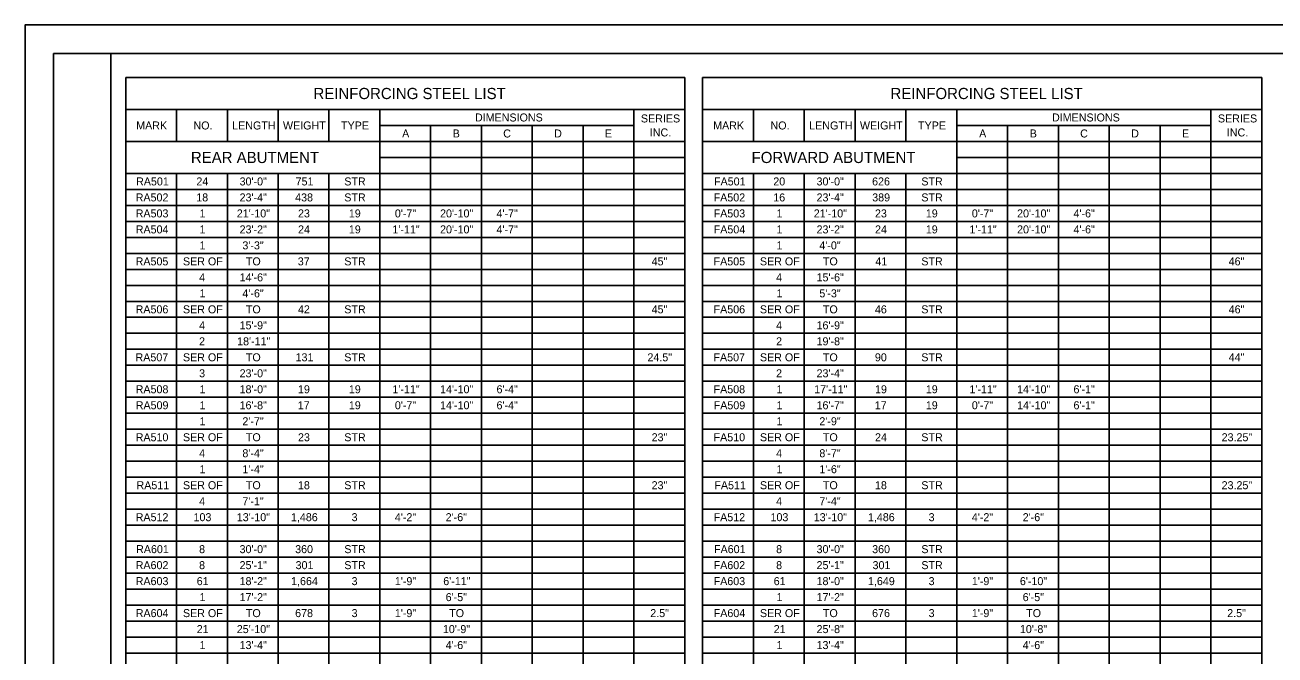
# Model space of a CAD drawing. Extents: x 0 to 34, y 0 to 22.
# Drawn here: x 0 to 21.87, y 10.97 to 22 of the extents above; entities that cross this region are included whole.
import ezdxf

# ---------------------------------------------------------------- set-up
doc = ezdxf.new("R2010")
doc.units = 0
for name, color, linetype in [('Default', 7, 'Continuous'), ('SH_Border', 7, 'Continuous'), ('SH_Cut_Line', 7, 'Continuous')]:
    doc.layers.add(name, color=color, linetype=linetype)

msp = doc.modelspace()

# ---------------------------------------------------------------- linework, layer by layer
at = {"layer": 'Default'}
for p, q in [((1.762, 21.08), (11.545, 21.08)), ((1.762, 21.08), (1.762, 0.92)), ((11.545, 21.08), (11.545, 0.92)), ((11.858, 21.08), (21.642, 21.08)), ((11.858, 21.08), (11.858, 0.92)), ((21.642, 21.08), (21.642, 0.92)), ((1.762, 20.52), (11.545, 20.52)), ((2.651, 20.52), (2.651, 19.96)), ((3.541, 20.52), (3.541, 19.96)), ((4.43, 20.52), (4.43, 19.96)), ((5.319, 20.52), (5.319, 19.96)), ((6.209, 20.52), (6.209, 2.04)), ((10.656, 20.52), (10.656, 2.04)), ((11.858, 20.52), (21.642, 20.52)), ((12.748, 20.52), (12.748, 19.96)), ((13.637, 20.52), (13.637, 19.96)), ((14.526, 20.52), (14.526, 19.96)), ((15.416, 20.52), (15.416, 19.96)), ((16.305, 20.52), (16.305, 2.04)), ((20.752, 20.52), (20.752, 2.04)), ((6.209, 20.24), (10.656, 20.24)), ((7.098, 20.24), (7.098, 2.04)), ((7.988, 20.24), (7.988, 2.04)), ((8.877, 20.24), (8.877, 2.04)), ((9.766, 20.24), (9.766, 2.04)), ((16.305, 20.24), (20.752, 20.24)), ((17.195, 20.24), (17.195, 2.04)), ((18.084, 20.24), (18.084, 2.04)), ((18.974, 20.24), (18.974, 2.04)), ((19.863, 20.24), (19.863, 2.04)), ((1.762, 19.96), (11.545, 19.96)), ((11.858, 19.96), (21.642, 19.96)), ((6.209, 19.68), (11.545, 19.68)), ((16.305, 19.68), (21.642, 19.68)), ((1.762, 19.4), (6.209, 19.4)), ((2.651, 19.4), (2.651, 7.08)), ((3.541, 19.4), (3.541, 7.08)), ((4.43, 19.4), (4.43, 7.08)), ((5.319, 19.4), (5.319, 7.08)), ((6.209, 19.4), (11.545, 19.4)), ((11.858, 19.4), (16.305, 19.4)), ((12.748, 19.4), (12.748, 7.08)), ((13.637, 19.4), (13.637, 7.08)), ((14.526, 19.4), (14.526, 7.08)), ((15.416, 19.4), (15.416, 7.08)), ((16.305, 19.4), (21.642, 19.4)), ((1.762, 19.12), (11.545, 19.12)), ((11.858, 19.12), (21.642, 19.12)), ((1.762, 18.84), (11.545, 18.84)), ((11.858, 18.84), (21.642, 18.84)), ((1.762, 18.56), (11.545, 18.56)), ((11.858, 18.56), (21.642, 18.56)), ((1.762, 18.28), (11.545, 18.28)), ((11.858, 18.28), (21.642, 18.28)), ((1.762, 18), (11.545, 18)), ((11.858, 18), (21.642, 18)), ((1.762, 17.72), (11.545, 17.72)), ((11.858, 17.72), (21.642, 17.72)), ((1.762, 17.44), (11.545, 17.44)), ((11.858, 17.44), (21.642, 17.44)), ((1.762, 17.16), (11.545, 17.16)), ((11.858, 17.16), (21.642, 17.16)), ((1.762, 16.88), (11.545, 16.88)), ((11.858, 16.88), (21.642, 16.88)), ((1.762, 16.6), (11.545, 16.6)), ((11.858, 16.6), (21.642, 16.6)), ((1.762, 16.32), (11.545, 16.32)), ((11.858, 16.32), (21.642, 16.32)), ((1.762, 16.04), (11.545, 16.04)), ((11.858, 16.04), (21.642, 16.04)), ((1.762, 15.76), (11.545, 15.76)), ((11.858, 15.76), (21.642, 15.76)), ((1.762, 15.48), (11.545, 15.48)), ((11.858, 15.48), (21.642, 15.48)), ((1.762, 15.2), (11.545, 15.2)), ((11.858, 15.2), (21.642, 15.2)), ((1.762, 14.92), (11.545, 14.92)), ((11.858, 14.92), (21.642, 14.92)), ((1.762, 14.64), (11.545, 14.64)), ((11.858, 14.64), (21.642, 14.64)), ((1.762, 14.36), (11.545, 14.36)), ((11.858, 14.36), (21.642, 14.36)), ((1.762, 14.08), (11.545, 14.08)), ((11.858, 14.08), (21.642, 14.08)), ((1.762, 13.8), (11.545, 13.8)), ((11.858, 13.8), (21.642, 13.8)), ((1.762, 13.52), (11.545, 13.52)), ((11.858, 13.52), (21.642, 13.52)), ((1.762, 13.24), (11.545, 13.24)), ((11.858, 13.24), (21.642, 13.24)), ((1.762, 12.96), (11.545, 12.96)), ((11.858, 12.96), (21.642, 12.96)), ((1.762, 12.68), (11.545, 12.68)), ((11.858, 12.68), (21.642, 12.68)), ((1.762, 12.4), (11.545, 12.4)), ((11.858, 12.4), (21.642, 12.4)), ((1.762, 12.12), (11.545, 12.12)), ((11.858, 12.12), (21.642, 12.12)), ((1.762, 11.84), (11.545, 11.84)), ((11.858, 11.84), (21.642, 11.84)), ((1.762, 11.56), (11.545, 11.56)), ((11.858, 11.56), (21.642, 11.56)), ((1.762, 11.28), (11.545, 11.28)), ((11.858, 11.28), (21.642, 11.28)), ((1.762, 11), (11.545, 11)), ((11.858, 11), (21.642, 11))]:
    msp.add_line(p, q, dxfattribs=at)
at = {"layer": 'SH_Border'}
for points in [[(0.5, 21.5), (1.5, 21.5), (1.5, 0.5), (0.5, 0.5)], [(1.5, 21.5), (33.5, 21.5), (33.5, 0.5), (1.5, 0.5)]]:
    msp.add_lwpolyline(points, close=True, dxfattribs=at)
at = {"layer": 'SH_Cut_Line'}
msp.add_lwpolyline([(0, 0), (34, 0), (34, 22), (0, 22)], close=True, dxfattribs=at)

# ---------------------------------------------------------------- texts
at = {"layer": 'Default'}
for s, height, p in [('REINFORCING STEEL LIST', 0.196, (5.048, 20.702)), ('REINFORCING STEEL LIST', 0.196, (15.145, 20.702)), ('DIMENSIONS', 0.14, (7.874, 20.31)), ('SERIES ', 0.14, (10.777, 20.293)), ('DIMENSIONS', 0.14, (17.971, 20.31)), ('SERIES ', 0.14, (20.874, 20.293)), ('MARK', 0.14, (1.946, 20.17)), ('NO.', 0.14, (2.948, 20.17)), ('LENGTH', 0.14, (3.625, 20.17)), ('WEIGHT', 0.14, (4.514, 20.17)), ('TYPE', 0.14, (5.53, 20.17)), ('A', 0.14, (6.599, 20.03)), ('B', 0.14, (7.484, 20.03)), ('C', 0.14, (8.368, 20.03)), ('D', 0.14, (9.259, 20.03)), ('E', 0.14, (10.148, 20.03)), ('INC.', 0.14, (10.933, 20.048)), ('MARK', 0.14, (12.042, 20.17)), ('NO.', 0.14, (13.045, 20.17)), ('LENGTH', 0.14, (13.722, 20.17)), ('WEIGHT', 0.14, (14.61, 20.17)), ('TYPE', 0.14, (15.627, 20.17)), ('A', 0.14, (16.696, 20.03)), ('B', 0.14, (17.581, 20.03)), ('C', 0.14, (18.464, 20.03)), ('D', 0.14, (19.356, 20.03)), ('E', 0.14, (20.245, 20.03)), ('INC.', 0.14, (21.03, 20.048)), ('REAR ABUTMENT', 0.196, (2.903, 19.582)), ('FORWARD ABUTMENT', 0.196, (12.714, 19.582)), ('RA501', 0.14, (1.944, 19.19)), ('24', 0.14, (2.999, 19.19)), ('30\'-0"', 0.14, (3.755, 19.19)), ('751', 0.14, (4.735, 19.19)), ('STR', 0.14, (5.587, 19.19)), ('FA501', 0.14, (12.057, 19.19)), ('20', 0.14, (13.094, 19.19)), ('30\'-0"', 0.14, (13.851, 19.19)), ('626', 0.14, (14.823, 19.19)), ('STR', 0.14, (15.684, 19.19)), ('RA502', 0.14, (1.937, 18.91)), ('18', 0.14, (2.997, 18.91)), ('23\'-4"', 0.14, (3.755, 18.91)), ('438', 0.14, (4.727, 18.91)), ('STR', 0.14, (5.587, 18.91)), ('FA502', 0.14, (12.05, 18.91)), ('16', 0.14, (13.093, 18.91)), ('23\'-4"', 0.14, (13.851, 18.91)), ('389', 0.14, (14.825, 18.91)), ('STR', 0.14, (15.684, 18.91)), ('RA503', 0.14, (1.937, 18.63)), ('1', 0.14, (3.054, 18.63)), ('21\'-10"', 0.14, (3.706, 18.63)), ('23', 0.14, (4.777, 18.63)), ('19', 0.14, (5.667, 18.63)), ('0\'-7"', 0.14, (6.472, 18.63)), ('20\'-10"', 0.14, (7.263, 18.63)), ('4\'-7"', 0.14, (8.251, 18.63)), ('FA503', 0.14, (12.05, 18.63)), ('1', 0.14, (13.15, 18.63)), ('21\'-10"', 0.14, (13.802, 18.63)), ('23', 0.14, (14.873, 18.63)), ('19', 0.14, (15.763, 18.63)), ('0\'-7"', 0.14, (16.568, 18.63)), ('20\'-10"', 0.14, (17.36, 18.63)), ('4\'-6"', 0.14, (18.347, 18.63)), ('RA504', 0.14, (1.938, 18.35)), ('1', 0.14, (3.054, 18.35)), ('23\'-2"', 0.14, (3.755, 18.35)), ('24', 0.14, (4.778, 18.35)), ('19', 0.14, (5.667, 18.35)), ('1\'-11"', 0.14, (6.429, 18.35)), ('20\'-10"', 0.14, (7.263, 18.35)), ('4\'-7"', 0.14, (8.251, 18.35)), ('FA504', 0.14, (12.051, 18.35)), ('1', 0.14, (13.15, 18.35)), ('23\'-2"', 0.14, (13.851, 18.35)), ('24', 0.14, (14.874, 18.35)), ('19', 0.14, (15.763, 18.35)), ('1\'-11"', 0.14, (16.526, 18.35)), ('20\'-10"', 0.14, (17.36, 18.35)), ('4\'-6"', 0.14, (18.347, 18.35)), ('1', 0.14, (3.054, 18.07)), ('3\'-3"', 0.14, (3.804, 18.07)), ('1', 0.14, (13.15, 18.07)), ('4\'-0"', 0.14, (13.9, 18.07)), ('RA505', 0.14, (1.936, 17.79)), ('SER OF', 0.14, (2.764, 17.79)), ('TO', 0.14, (3.865, 17.79)), ('37', 0.14, (4.773, 17.79)), ('STR', 0.14, (5.587, 17.79)), ('45"', 0.14, (10.965, 17.79)), ('FA505', 0.14, (12.049, 17.79)), ('SER OF', 0.14, (12.86, 17.79)), ('TO', 0.14, (13.962, 17.79)), ('41', 0.14, (14.88, 17.79)), ('STR', 0.14, (15.684, 17.79)), ('46"', 0.14, (21.062, 17.79)), ('4', 0.14, (3.048, 17.51)), ('14\'-6"', 0.14, (3.755, 17.51)), ('4', 0.14, (13.144, 17.51)), ('15\'-6"', 0.14, (13.851, 17.51)), ('1', 0.14, (3.054, 17.23)), ('4\'-6"', 0.14, (3.804, 17.23)), ('1', 0.14, (13.15, 17.23)), ('5\'-3"', 0.14, (13.9, 17.23)), ('RA506', 0.14, (1.936, 16.95)), ('SER OF', 0.14, (2.764, 16.95)), ('TO', 0.14, (3.865, 16.95)), ('42', 0.14, (4.776, 16.95)), ('STR', 0.14, (5.587, 16.95)), ('45"', 0.14, (10.965, 16.95)), ('FA506', 0.14, (12.049, 16.95)), ('SER OF', 0.14, (12.86, 16.95)), ('TO', 0.14, (13.962, 16.95)), ('46', 0.14, (14.872, 16.95)), ('STR', 0.14, (15.684, 16.95)), ('46"', 0.14, (21.062, 16.95)), ('4', 0.14, (3.048, 16.67)), ('15\'-9"', 0.14, (3.755, 16.67)), ('4', 0.14, (13.144, 16.67)), ('16\'-9"', 0.14, (13.851, 16.67)), ('2', 0.14, (3.046, 16.39)), ('18\'-11"', 0.14, (3.712, 16.39)), ('2', 0.14, (13.143, 16.39)), ('19\'-8"', 0.14, (13.851, 16.39)), ('RA507', 0.14, (1.934, 16.11)), ('SER OF', 0.14, (2.764, 16.11)), ('TO', 0.14, (3.865, 16.11)), ('131', 0.14, (4.735, 16.11)), ('STR', 0.14, (5.587, 16.11)), ('24.5"', 0.14, (10.892, 16.11)), ('FA507', 0.14, (12.047, 16.11)), ('SER OF', 0.14, (12.86, 16.11)), ('TO', 0.14, (13.962, 16.11)), ('90', 0.14, (14.872, 16.11)), ('STR', 0.14, (15.684, 16.11)), ('44"', 0.14, (21.062, 16.11)), ('3', 0.14, (3.047, 15.83)), ('23\'-0"', 0.14, (3.755, 15.83)), ('2', 0.14, (13.143, 15.83)), ('23\'-4"', 0.14, (13.851, 15.83)), ('RA508', 0.14, (1.937, 15.55)), ('1', 0.14, (3.054, 15.55)), ('18\'-0"', 0.14, (3.755, 15.55)), ('19', 0.14, (4.777, 15.55)), ('19', 0.14, (5.667, 15.55)), ('1\'-11"', 0.14, (6.429, 15.55)), ('14\'-10"', 0.14, (7.263, 15.55)), ('6\'-4"', 0.14, (8.251, 15.55)), ('FA508', 0.14, (12.049, 15.55)), ('1', 0.14, (13.15, 15.55)), ('17\'-11"', 0.14, (13.809, 15.55)), ('19', 0.14, (14.874, 15.55)), ('19', 0.14, (15.763, 15.55)), ('1\'-11"', 0.14, (16.526, 15.55)), ('14\'-10"', 0.14, (17.36, 15.55)), ('6\'-1"', 0.14, (18.347, 15.55)), ('RA509', 0.14, (1.938, 15.27)), ('1', 0.14, (3.054, 15.27)), ('16\'-8"', 0.14, (3.755, 15.27)), ('17', 0.14, (4.773, 15.27)), ('19', 0.14, (5.667, 15.27)), ('0\'-7"', 0.14, (6.472, 15.27)), ('14\'-10"', 0.14, (7.263, 15.27)), ('6\'-4"', 0.14, (8.251, 15.27)), ('FA509', 0.14, (12.051, 15.27)), ('1', 0.14, (13.15, 15.27)), ('16\'-7"', 0.14, (13.851, 15.27)), ('17', 0.14, (14.87, 15.27)), ('19', 0.14, (15.763, 15.27)), ('0\'-7"', 0.14, (16.568, 15.27)), ('14\'-10"', 0.14, (17.36, 15.27)), ('6\'-1"', 0.14, (18.347, 15.27)), ('1', 0.14, (3.054, 14.99)), ('2\'-7"', 0.14, (3.804, 14.99)), ('1', 0.14, (13.15, 14.99)), ('2\'-9"', 0.14, (13.9, 14.99)), ('RA510', 0.14, (1.937, 14.71)), ('SER OF', 0.14, (2.764, 14.71)), ('TO', 0.14, (3.865, 14.71)), ('23', 0.14, (4.777, 14.71)), ('STR', 0.14, (5.587, 14.71)), ('23"', 0.14, (10.965, 14.71)), ('FA510', 0.14, (12.049, 14.71)), ('SER OF', 0.14, (12.86, 14.71)), ('TO', 0.14, (13.962, 14.71)), ('24', 0.14, (14.874, 14.71)), ('STR', 0.14, (15.684, 14.71)), ('23.25"', 0.14, (20.939, 14.71)), ('4', 0.14, (3.048, 14.43)), ('8\'-4"', 0.14, (3.804, 14.43)), ('4', 0.14, (13.144, 14.43)), ('8\'-7"', 0.14, (13.9, 14.43)), ('1', 0.14, (3.054, 14.15)), ('1\'-4"', 0.14, (3.804, 14.15)), ('1', 0.14, (13.15, 14.15)), ('1\'-6"', 0.14, (13.9, 14.15)), ('RA511', 0.14, (1.951, 13.87)), ('SER OF', 0.14, (2.764, 13.87)), ('TO', 0.14, (3.865, 13.87)), ('18', 0.14, (4.776, 13.87)), ('STR', 0.14, (5.587, 13.87)), ('23"', 0.14, (10.965, 13.87)), ('FA511', 0.14, (12.063, 13.87)), ('SER OF', 0.14, (12.86, 13.87)), ('TO', 0.14, (13.962, 13.87)), ('18', 0.14, (14.873, 13.87)), ('STR', 0.14, (15.684, 13.87)), ('23.25"', 0.14, (20.939, 13.87)), ('4', 0.14, (3.048, 13.59)), ('7\'-1"', 0.14, (3.804, 13.59)), ('4', 0.14, (13.144, 13.59)), ('7\'-4"', 0.14, (13.9, 13.59)), ('RA512', 0.14, (1.937, 13.31)), ('103', 0.14, (2.949, 13.31)), ('13\'-10"', 0.14, (3.706, 13.31)), ('1,486', 0.14, (4.654, 13.31)), ('3', 0.14, (5.715, 13.31)), ('4\'-2"', 0.14, (6.472, 13.31)), ('2\'-6"', 0.14, (7.361, 13.31)), ('FA512', 0.14, (12.05, 13.31)), ('103', 0.14, (13.045, 13.31)), ('13\'-10"', 0.14, (13.802, 13.31)), ('1,486', 0.14, (14.75, 13.31)), ('3', 0.14, (15.812, 13.31)), ('4\'-2"', 0.14, (16.568, 13.31)), ('2\'-6"', 0.14, (17.458, 13.31)), ('RA601', 0.14, (1.944, 12.75)), ('8', 0.14, (3.046, 12.75)), ('30\'-0"', 0.14, (3.755, 12.75)), ('360', 0.14, (4.727, 12.75)), ('STR', 0.14, (5.587, 12.75)), ('FA601', 0.14, (12.057, 12.75)), ('8', 0.14, (13.143, 12.75)), ('30\'-0"', 0.14, (13.851, 12.75)), ('360', 0.14, (14.824, 12.75)), ('STR', 0.14, (15.684, 12.75)), ('RA602', 0.14, (1.937, 12.47)), ('8', 0.14, (3.046, 12.47)), ('25\'-1"', 0.14, (3.755, 12.47)), ('301', 0.14, (4.735, 12.47)), ('STR', 0.14, (5.587, 12.47)), ('FA602', 0.14, (12.05, 12.47)), ('8', 0.14, (13.143, 12.47)), ('25\'-1"', 0.14, (13.851, 12.47)), ('301', 0.14, (14.831, 12.47)), ('STR', 0.14, (15.684, 12.47)), ('RA603', 0.14, (1.937, 12.19)), ('61', 0.14, (3.005, 12.19)), ('18\'-2"', 0.14, (3.755, 12.19)), ('1,664', 0.14, (4.656, 12.19)), ('3', 0.14, (5.715, 12.19)), ('1\'-9"', 0.14, (6.472, 12.19)), ('6\'-11"', 0.14, (7.319, 12.19)), ('FA603', 0.14, (12.05, 12.19)), ('61', 0.14, (13.101, 12.19)), ('18\'-0"', 0.14, (13.851, 12.19)), ('1,649', 0.14, (14.751, 12.19)), ('3', 0.14, (15.812, 12.19)), ('1\'-9"', 0.14, (16.568, 12.19)), ('6\'-10"', 0.14, (17.409, 12.19)), ('1', 0.14, (3.054, 11.91)), ('17\'-2"', 0.14, (3.755, 11.91)), ('6\'-5"', 0.14, (7.361, 11.91)), ('1', 0.14, (13.15, 11.91)), ('17\'-2"', 0.14, (13.851, 11.91)), ('6\'-5"', 0.14, (17.458, 11.91)), ('RA604', 0.14, (1.938, 11.63)), ('SER OF', 0.14, (2.764, 11.63)), ('TO', 0.14, (3.865, 11.63)), ('678', 0.14, (4.727, 11.63)), ('3', 0.14, (5.715, 11.63)), ('1\'-9"', 0.14, (6.472, 11.63)), ('TO', 0.14, (7.423, 11.63)), ('2.5"', 0.14, (10.941, 11.63)), ('FA604', 0.14, (12.051, 11.63)), ('SER OF', 0.14, (12.86, 11.63)), ('TO', 0.14, (13.962, 11.63)), ('676', 0.14, (14.823, 11.63)), ('3', 0.14, (15.812, 11.63)), ('1\'-9"', 0.14, (16.568, 11.63)), ('TO', 0.14, (17.519, 11.63)), ('2.5"', 0.14, (21.037, 11.63)), ('21', 0.14, (3.005, 11.35)), ('25\'-10"', 0.14, (3.706, 11.35)), ('10\'-9"', 0.14, (7.312, 11.35)), ('21', 0.14, (13.101, 11.35)), ('25\'-8"', 0.14, (13.851, 11.35)), ('10\'-8"', 0.14, (17.409, 11.35)), ('1', 0.14, (3.054, 11.07)), ('13\'-4"', 0.14, (3.755, 11.07)), ('4\'-6"', 0.14, (7.361, 11.07)), ('1', 0.14, (13.15, 11.07)), ('13\'-4"', 0.14, (13.851, 11.07)), ('4\'-6"', 0.14, (17.458, 11.07))]:
    msp.add_text(s, height=height, dxfattribs=at).set_placement(p)

doc.saveas('drawing.dxf')
